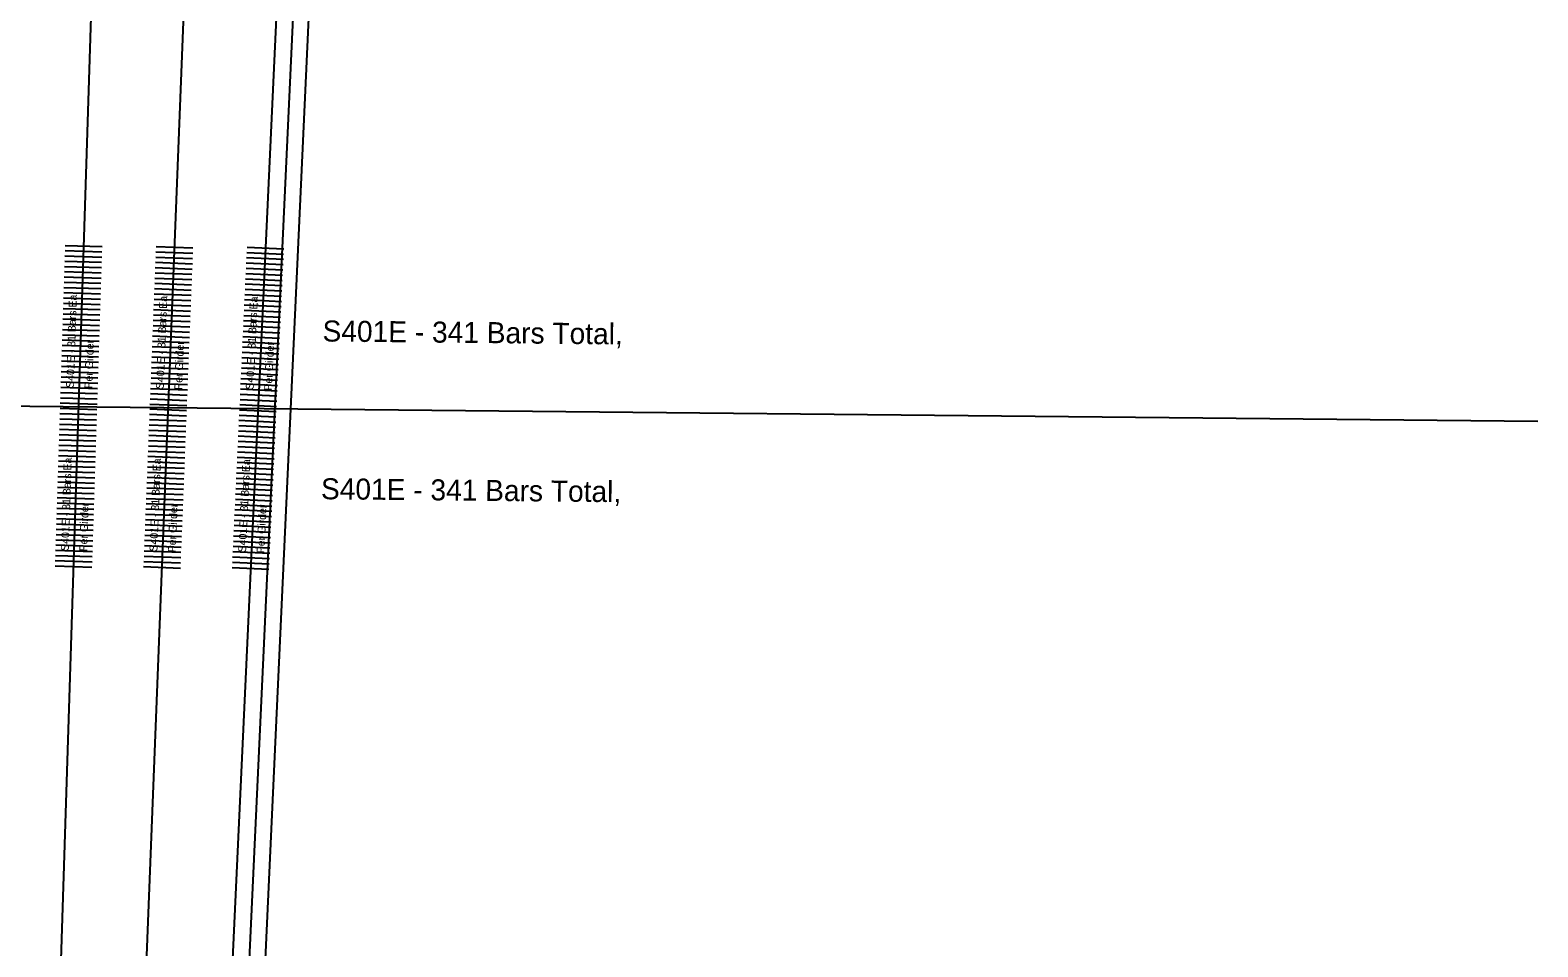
# Model space of a CAD drawing. Extents: x 632276 to 635000, y 381313 to 381846.
# Drawn here: x 634855.3 to 634998.6, y 381439 to 381526.1 of the extents above; entities that cross this region are included whole.
import ezdxf

# ---------------------------------------------------------------- set-up
doc = ezdxf.new("R2010")
doc.units = 0
for name, color, linetype in [('B_Boring Annot', 7, 'Continuous'), ('B_No_Plot', 7, 'Continuous'), ('R_Border_Scale', 7, 'Continuous'), ('R_Shade Removal', 7, 'Continuous'), ('R_Wall', 7, 'Continuous')]:
    doc.layers.add(name, color=color, linetype=linetype)

msp = doc.modelspace()

# ---------------------------------------------------------------- linework, layer by layer
at = {"layer": 'B_Boring Annot'}
for p, q in [((634874.43, 381400.26), (634884.62, 381620.17)), ((634875.93, 381400.19), (634886.11, 381620.1))]:
    msp.add_line(p, q, dxfattribs=at)
at = {"layer": 'B_No_Plot'}
msp.add_line((634670, 381492.24), (634998.64, 381488.97), dxfattribs=at)
at = {"layer": 'R_Border_Scale'}
for p, q in [((634862.13, 381505.04), (634858.63, 381505.15)), ((634862.15, 381505.54), (634858.65, 381505.65)), ((634870.76, 381504.9), (634867.27, 381505.04)), ((634870.78, 381505.4), (634867.29, 381505.53)), ((634879.4, 381504.82), (634875.9, 381504.98)), ((634879.42, 381505.32), (634875.93, 381505.48)), ((634862.08, 381503.54), (634858.58, 381503.65)), ((634862.1, 381504.04), (634858.6, 381504.15)), ((634862.11, 381504.54), (634858.62, 381504.65)), ((634870.71, 381503.4), (634867.21, 381503.54)), ((634870.73, 381503.9), (634867.23, 381504.04)), ((634870.74, 381504.4), (634867.25, 381504.54)), ((634879.33, 381503.32), (634875.83, 381503.48)), ((634879.35, 381503.82), (634875.86, 381503.98)), ((634879.38, 381504.32), (634875.88, 381504.48)), ((634862.04, 381502.04), (634858.54, 381502.15)), ((634862.05, 381502.54), (634858.55, 381502.65)), ((634862.07, 381503.04), (634858.57, 381503.15)), ((634870.65, 381501.9), (634867.15, 381502.04)), ((634870.67, 381502.4), (634867.17, 381502.54)), ((634870.69, 381502.9), (634867.19, 381503.04)), ((634879.26, 381501.82), (634875.76, 381501.99)), ((634879.28, 381502.32), (634875.79, 381502.48)), ((634879.31, 381502.82), (634875.81, 381502.98)), ((634861.99, 381500.54), (634858.49, 381500.65)), ((634862, 381501.04), (634858.51, 381501.15)), ((634862.02, 381501.54), (634858.52, 381501.65)), ((634870.59, 381500.4), (634867.09, 381500.54)), ((634870.61, 381500.9), (634867.11, 381501.04)), ((634870.63, 381501.4), (634867.13, 381501.54)), ((634879.21, 381500.82), (634875.72, 381500.99)), ((634879.24, 381501.32), (634875.74, 381501.49)), ((634861.94, 381499.04), (634858.44, 381499.15)), ((634861.96, 381499.54), (634858.46, 381499.65)), ((634861.97, 381500.04), (634858.47, 381500.15)), ((634870.55, 381499.4), (634867.05, 381499.54)), ((634870.57, 381499.9), (634867.07, 381500.04)), ((634879.15, 381499.33), (634875.65, 381499.49)), ((634879.17, 381499.83), (634875.67, 381499.99)), ((634879.19, 381500.32), (634875.7, 381500.49)), ((634861.89, 381497.54), (634858.39, 381497.65)), ((634861.91, 381498.04), (634858.41, 381498.15)), ((634861.92, 381498.54), (634858.43, 381498.65)), ((634870.49, 381497.9), (634866.99, 381498.04)), ((634870.51, 381498.4), (634867.01, 381498.54)), ((634870.53, 381498.9), (634867.03, 381499.04)), ((634879.08, 381497.83), (634875.58, 381497.99)), ((634879.1, 381498.33), (634875.6, 381498.49)), ((634879.12, 381498.83), (634875.63, 381498.99)), ((634861.86, 381496.54), (634858.36, 381496.65)), ((634861.88, 381497.04), (634858.38, 381497.15)), ((634870.43, 381496.4), (634866.93, 381496.54)), ((634870.45, 381496.9), (634866.95, 381497.04)), ((634870.47, 381497.4), (634866.97, 381497.54)), ((634879.01, 381496.33), (634875.51, 381496.49)), ((634879.03, 381496.83), (634875.53, 381496.99)), ((634879.05, 381497.33), (634875.56, 381497.49)), ((634861.81, 381495.04), (634858.31, 381495.16)), ((634861.83, 381495.54), (634858.33, 381495.66)), ((634861.84, 381496.04), (634858.35, 381496.15)), ((634870.37, 381494.91), (634866.88, 381495.04)), ((634870.39, 381495.41), (634866.9, 381495.54)), ((634870.41, 381495.91), (634866.91, 381496.04)), ((634878.94, 381494.83), (634875.44, 381494.99)), ((634878.96, 381495.33), (634875.46, 381495.49)), ((634878.98, 381495.83), (634875.49, 381495.99)), ((634861.77, 381493.54), (634858.27, 381493.66)), ((634861.78, 381494.04), (634858.28, 381494.16)), ((634861.8, 381494.54), (634858.3, 381494.66)), ((634870.31, 381493.41), (634866.82, 381493.54)), ((634870.33, 381493.91), (634866.84, 381494.04)), ((634870.35, 381494.41), (634866.86, 381494.54)), ((634878.87, 381493.33), (634875.37, 381493.49)), ((634878.89, 381493.83), (634875.39, 381493.99)), ((634878.91, 381494.33), (634875.42, 381494.49)), ((634861.72, 381492.05), (634858.22, 381492.16)), ((634861.73, 381492.55), (634858.24, 381492.66)), ((634861.75, 381493.05), (634858.25, 381493.16)), ((634870.26, 381491.91), (634866.76, 381492.05)), ((634870.28, 381492.41), (634866.78, 381492.54)), ((634870.29, 381492.91), (634866.8, 381493.04)), ((634878.8, 381491.83), (634875.3, 381492)), ((634878.82, 381492.33), (634875.32, 381492.5)), ((634878.84, 381492.83), (634875.35, 381492.99)), ((634861.67, 381490.55), (634858.17, 381490.66)), ((634861.69, 381491.05), (634858.19, 381491.16)), ((634861.7, 381491.55), (634858.2, 381491.66)), ((634870.2, 381490.41), (634866.7, 381490.55)), ((634870.22, 381490.91), (634866.72, 381491.05)), ((634870.24, 381491.41), (634866.74, 381491.55)), ((634878.73, 381490.34), (634875.23, 381490.5)), ((634878.75, 381490.84), (634875.26, 381491)), ((634878.77, 381491.33), (634875.28, 381491.5)), ((634861.62, 381489.05), (634858.12, 381489.16)), ((634861.64, 381489.55), (634858.14, 381489.66)), ((634861.65, 381490.05), (634858.16, 381490.16)), ((634870.14, 381488.95), (634866.64, 381489.09)), ((634870.16, 381489.45), (634866.66, 381489.59)), ((634870.18, 381489.95), (634866.68, 381490.09)), ((634878.68, 381489.35), (634875.19, 381489.51)), ((634878.71, 381489.85), (634875.21, 381490.01)), ((634861.57, 381487.55), (634858.08, 381487.66)), ((634861.59, 381488.05), (634858.09, 381488.16)), ((634861.61, 381488.55), (634858.11, 381488.66)), ((634870.1, 381487.95), (634866.6, 381488.09)), ((634870.12, 381488.45), (634866.62, 381488.59)), ((634878.61, 381487.85), (634875.12, 381488.02)), ((634878.64, 381488.35), (634875.14, 381488.52)), ((634878.66, 381488.85), (634875.16, 381489.01)), ((634861.54, 381486.55), (634858.04, 381486.66)), ((634861.56, 381487.05), (634858.06, 381487.16)), ((634870.04, 381486.45), (634866.55, 381486.59)), ((634870.06, 381486.95), (634866.57, 381487.09)), ((634870.08, 381487.45), (634866.59, 381487.59)), ((634878.54, 381486.36), (634875.05, 381486.52)), ((634878.57, 381486.86), (634875.07, 381487.02)), ((634878.59, 381487.35), (634875.09, 381487.52)), ((634861.5, 381485.05), (634858, 381485.16)), ((634861.51, 381485.55), (634858.01, 381485.66)), ((634861.53, 381486.05), (634858.03, 381486.16)), ((634869.98, 381484.95), (634866.49, 381485.09)), ((634870, 381485.45), (634866.51, 381485.59)), ((634870.02, 381485.95), (634866.53, 381486.09)), ((634878.48, 381484.86), (634874.98, 381485.02)), ((634878.5, 381485.36), (634875, 381485.52)), ((634878.52, 381485.86), (634875.03, 381486.02)), ((634861.45, 381483.55), (634857.95, 381483.66)), ((634861.46, 381484.05), (634857.97, 381484.16)), ((634861.48, 381484.55), (634857.98, 381484.66)), ((634869.93, 381483.45), (634866.43, 381483.59)), ((634869.95, 381483.95), (634866.45, 381484.09)), ((634869.97, 381484.45), (634866.47, 381484.59)), ((634878.41, 381483.36), (634874.91, 381483.52)), ((634878.43, 381483.86), (634874.93, 381484.02)), ((634878.45, 381484.36), (634874.96, 381484.52)), ((634861.4, 381482.05), (634857.9, 381482.16)), ((634861.42, 381482.55), (634857.92, 381482.66)), ((634861.43, 381483.05), (634857.93, 381483.16)), ((634869.87, 381481.96), (634866.37, 381482.09)), ((634869.89, 381482.45), (634866.39, 381482.59)), ((634869.91, 381482.95), (634866.41, 381483.09)), ((634878.34, 381481.86), (634874.84, 381482.02)), ((634878.36, 381482.36), (634874.86, 381482.52)), ((634878.38, 381482.86), (634874.89, 381483.02)), ((634861.35, 381480.55), (634857.85, 381480.66)), ((634861.37, 381481.05), (634857.87, 381481.16)), ((634861.38, 381481.55), (634857.89, 381481.66)), ((634869.81, 381480.46), (634866.31, 381480.59)), ((634869.83, 381480.96), (634866.33, 381481.09)), ((634869.85, 381481.46), (634866.35, 381481.59)), ((634878.27, 381480.36), (634874.77, 381480.52)), ((634878.29, 381480.86), (634874.79, 381481.02)), ((634878.31, 381481.36), (634874.82, 381481.52)), ((634861.3, 381479.05), (634857.81, 381479.16)), ((634861.32, 381479.55), (634857.82, 381479.66)), ((634861.34, 381480.05), (634857.84, 381480.16)), ((634869.75, 381478.96), (634866.25, 381479.09)), ((634869.77, 381479.46), (634866.27, 381479.59)), ((634869.79, 381479.96), (634866.29, 381480.09)), ((634878.2, 381478.86), (634874.7, 381479.03)), ((634878.22, 381479.36), (634874.72, 381479.53)), ((634878.24, 381479.86), (634874.75, 381480.02)), ((634861.26, 381477.55), (634857.76, 381477.66)), ((634861.27, 381478.05), (634857.77, 381478.16)), ((634861.29, 381478.55), (634857.79, 381478.66)), ((634869.69, 381477.46), (634866.19, 381477.6)), ((634869.71, 381477.96), (634866.21, 381478.1)), ((634869.73, 381478.46), (634866.23, 381478.59)), ((634878.15, 381477.86), (634874.65, 381478.03)), ((634878.17, 381478.36), (634874.68, 381478.53)), ((634861.21, 381476.05), (634857.71, 381476.16)), ((634861.23, 381476.55), (634857.73, 381476.66)), ((634861.24, 381477.05), (634857.74, 381477.16)), ((634869.65, 381476.46), (634866.16, 381476.6)), ((634869.67, 381476.96), (634866.17, 381477.1)), ((634878.08, 381476.37), (634874.59, 381476.53)), ((634878.1, 381476.87), (634874.61, 381477.03)), ((634878.13, 381477.37), (634874.63, 381477.53)), ((634861.18, 381475.05), (634857.68, 381475.17)), ((634861.19, 381475.55), (634857.7, 381475.67)), ((634869.59, 381474.96), (634866.1, 381475.1)), ((634869.61, 381475.46), (634866.12, 381475.6)), ((634869.63, 381475.96), (634866.14, 381476.1)), ((634878.01, 381474.87), (634874.52, 381475.03)), ((634878.04, 381475.37), (634874.54, 381475.53)), ((634878.06, 381475.87), (634874.56, 381476.03))]:
    msp.add_line(p, q, dxfattribs=at)
at = {"layer": 'R_Shade Removal'}
for p, q in [((634864.04, 381620.32), (634857.05, 381400.38)), ((634864.93, 381400.3), (634873.52, 381620.22)), ((634882.99, 381620.13), (634872.8, 381400.22))]:
    msp.add_line(p, q, dxfattribs=at)

# ---------------------------------------------------------------- texts
at = {"layer": 'R_Wall'}
for s, height, rotation, p in [('S401E - 31 Bars Ea,', 0.75, 88.19, (634859.47, 381492.12)), ('S401E - 31 Bars Ea,', 0.75, 87.7697, (634868.01, 381492)), ('S401E - 31 Bars Ea,', 0.75, 87.3558, (634876.55, 381491.94)), ('S401E - 341 Bars Total,', 2, 359.4304, (634883.1, 381496.54)), ('Per Girder', 0.75, 88.19, (634861.22, 381492.06)), ('Per Girder', 0.75, 87.7697, (634869.76, 381491.93)), ('Per Girder', 0.75, 87.3558, (634878.3, 381491.86)), ('S401E - 31 Bars Ea,', 0.75, 88.19, (634858.98, 381476.62)), ('S401E - 31 Bars Ea,', 0.75, 87.7697, (634867.4, 381476.55)), ('S401E - 31 Bars Ea,', 0.75, 87.3558, (634875.83, 381476.47)), ('S401E - 341 Bars Total,', 2, 359.4304, (634882.95, 381481.54)), ('Per Girder', 0.75, 88.19, (634860.73, 381476.57)), ('Per Girder', 0.75, 87.7697, (634869.15, 381476.48)), ('Per Girder', 0.75, 87.3558, (634877.58, 381476.39))]:
    msp.add_text(s, height=height, rotation=rotation, dxfattribs=at).set_placement(p)

doc.saveas('drawing.dxf')
